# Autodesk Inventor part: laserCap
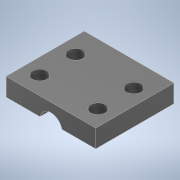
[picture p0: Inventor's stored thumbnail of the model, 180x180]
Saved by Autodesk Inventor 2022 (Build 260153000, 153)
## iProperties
Created: 2022-11
Part Number: laserCap
Material: Acetal Resin, Black
Document SubType Name: Modeling
Designer: Wojtus
Density: 1.425 g/cm^3
Appearance: Smooth - Black
Author: Wojtus
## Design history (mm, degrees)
sketch "Sketch2"
  geometry: L1 (-10, 2)-(10, 2); L2 (10, 2)-(10, -2); L3 (10, -2)-(-10, -2); L4 (-10, -2)-(-10, 2); L5 (-10, 2)-(10, -2); L6 (10, 2)-(-10, -2); C1 r 2.5 at (0, -2.5); 3 further points
  constraints: 12 end point, 2 midpoint, 2 parallel, 1 centre point, 1 horizontal, 1 perpendicular
  dimensions: "d2" = 20 distance of L2.end L3.end; "d3" = 4 distance of L1.end L2.end; "d4" = 5 diameter of C1; "d5" = 0.5 distance from line of L3 C1.centre; "d6" = 10 distance from line of L4 C1.centre (= 0.5 x d2)
extrude "Extrusion1" new body sketch "Sketch2" stored distance "d7" = 17.447; taper "d8" = 0 deg
sketch "Sketch3"
  geometry: L1 (20, 0)-(0, 0) reference; L2 (0, 17.447)-(0, 0) reference; C1 r 1.6 at (3.5, 4); C2 r 1.6 at (3.5, 12); C3 r 1.6 at (16.5, 4); C4 r 1.6 at (16.5, 12); 1 further point
  constraints: 4 centre point, 1 horizontal, 1 vertical, 6 other
  dimensions: "d9" = 3.2 diameter of C1; "d10" = 4 distance from line of L1 C1.centre; "d11" = 3.5 distance from line of L2 C1.centre; "d14" = 8 distance of C1.centre C2.centre; "d17" = 13 distance of C1.centre C3.centre
extrude "Extrusion2" cut sketch "Sketch3" extent not by distance; stored distance "d20" = 0; taper "d21" = 0 deg
body "Solid1"
